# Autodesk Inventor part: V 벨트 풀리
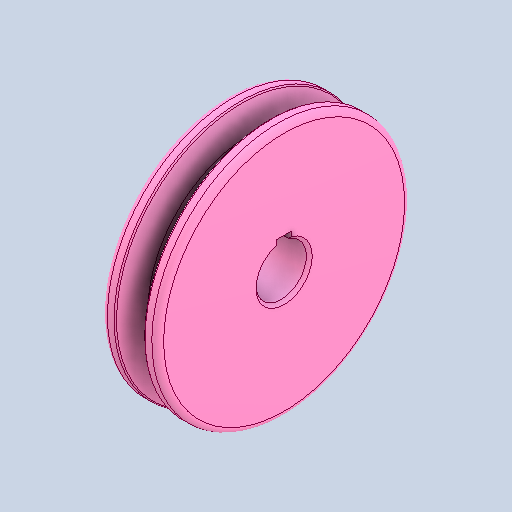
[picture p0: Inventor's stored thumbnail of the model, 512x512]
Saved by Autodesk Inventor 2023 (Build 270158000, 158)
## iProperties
Created: 2025-03
Part Number: V 벨트 풀리
Material: 알루미늄 6061
Document SubType Name: Modeling
Designer: User
Density: 2.71 g/cm^3
Appearance: 기본값
Author: jhkim
Sending System: Autodesk Inventor 2025
Preprocessor: ST-DEVELOPER v20
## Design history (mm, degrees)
feature "솔리드1"
node "솔리드2"
